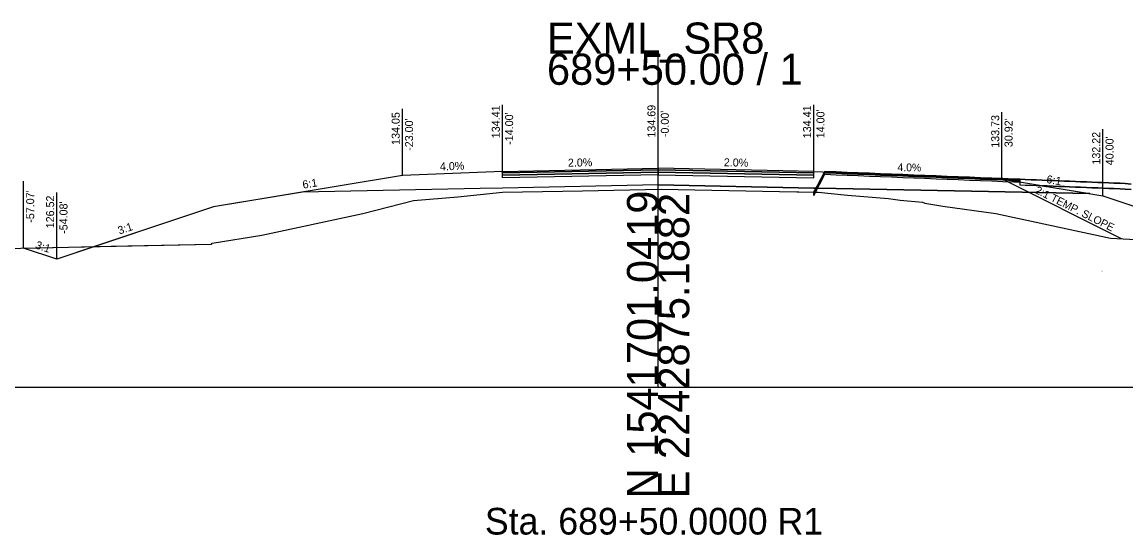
# Model space of a CAD drawing. Extents: x -26 to 1303, y -13 to 9563.
# Drawn here: x 92.8 to 192.1, y 4986.7 to 5032.8 of the extents above; entities that cross this region are included whole.
import ezdxf

# ---------------------------------------------------------------- set-up
doc = ezdxf.new("R2010")
doc.units = 0
for name, color, linetype in [('ASHPALT_12_5MM1', 7, 'Continuous'), ('ASPHALT_19MM1', 7, 'Continuous'), ('ASPHALT_9_5MM1', 7, 'Continuous'), ('CONST_LV3', 7, 'Continuous'), ('Default', 7, 'Continuous'), ('Draft_XS_Text', 7, 'Continuous'), ('DTM_P_FINISHED_GRADE', 7, 'Continuous'), ('DTM_TEMP_DROP', 7, 'Continuous'), ('DTM_X_BOUNDARY', 7, 'Continuous'), ('DTM_X_GROUND', 7, 'Continuous'), ('X_PROFILES_1', 7, 'Continuous'), ('XS_CELL', 7, 'Continuous'), ('XS_M_SHAPES_EARTHWORK', 7, 'Continuous'), ('XS_P_DR_ASPHALT', 7, 'Continuous'), ('XS_P_DR_ASPHALT_B', 7, 'Continuous'), ('XS_P_DR_GRAVEL', 7, 'Continuous'), ('XS_P_GROUND', 7, 'Continuous'), ('XS_P_SHOULDER', 7, 'Continuous'), ('XS_P_SUBGRADE_GRANULAR', 7, 'Continuous'), ('XS_P_TX_CLEARZONE', 7, 'Continuous'), ('XS_P_TX_FS_BS', 7, 'Continuous')]:
    doc.layers.add(name, color=color, linetype=linetype)

msp = doc.modelspace()

# ---------------------------------------------------------------- linework, layer by layer
at = {"layer": 'ASHPALT_12_5MM1'}
for points in [[(150, 5019.565), (150, 5019.355), (136, 5019.075), (136, 5019.285), (150, 5019.565)], [(150, 5019.565), (150, 5019.355), (164, 5019.075), (164, 5019.285), (150, 5019.565)]]:
    msp.add_lwpolyline(points, dxfattribs=at)
at = {"layer": 'ASPHALT_19MM1'}
for points in [[(150, 5019.355), (150, 5019.105), (136, 5018.825), (136, 5019.075), (150, 5019.355)], [(150, 5019.355), (150, 5019.105), (164, 5018.825), (164, 5019.075), (150, 5019.355)]]:
    msp.add_lwpolyline(points, dxfattribs=at)
at = {"layer": 'ASPHALT_9_5MM1'}
for points in [[(150, 5019.69), (150, 5019.565), (136, 5019.285), (136, 5019.41), (150, 5019.69)], [(150, 5019.69), (150, 5019.565), (164, 5019.285), (164, 5019.41), (150, 5019.69)]]:
    msp.add_lwpolyline(points, dxfattribs=at)
at = {"layer": 'CONST_LV3'}
msp.add_lwpolyline([(118, 5017.55), (110, 5016.216)], dxfattribs=at)
at = {"layer": 'DTM_P_FINISHED_GRADE'}
for points in [[(164, 5017.506), (165, 5019.405), (166, 5019.365), (167, 5019.325), (168, 5019.285), (169, 5019.245), (170, 5019.205), (171, 5019.165), (172, 5019.125), (173, 5019.085), (174, 5019.045), (175, 5019.005), (176, 5018.965), (177, 5018.925), (178, 5018.885), (179, 5018.845), (180, 5018.805), (181, 5018.765), (182, 5018.725), (182.543, 5018.704)], [(182.543, 5018.704), (183, 5018.685), (183.543, 5018.664), (184, 5018.645), (184.543, 5018.624), (185, 5018.605), (185.543, 5018.584), (186, 5018.565), (186.543, 5018.544), (187, 5018.525), (187.543, 5018.504), (188, 5018.485), (188.543, 5018.464), (189, 5018.445), (189.543, 5018.424), (190, 5018.405), (190.543, 5018.384), (191, 5018.365), (191.543, 5018.344), (192, 5018.325), (192.543, 5018.278)]]:
    msp.add_lwpolyline(points, dxfattribs=at)
at = {"layer": 'DTM_X_GROUND'}
msp.add_lwpolyline([(86.948, 5012.387), (96.964, 5012.61), (109.831, 5012.854), (109.9, 5012.954), (114.36, 5013.679), (123.451, 5015.61), (128.011, 5016.799), (131.983, 5017.133), (136.007, 5017.531), (143.203, 5017.677), (150.264, 5017.809), (160.911, 5017.613), (164.399, 5017.53), (167.029, 5017.267), (170.727, 5016.964), (171.762, 5016.835), (173.766, 5016.638), (173.979, 5016.565), (175.597, 5016.298), (180.383, 5015.638), (190.7, 5013.405), (200.917, 5012.876)], dxfattribs=at)
at = {"layer": 'XS_CELL'}
for p, q in [((150, 5000), (150, 5030)), ((0, 5000), (150, 5000)), ((150, 5000), (300, 5000))]:
    msp.add_line(p, q, dxfattribs=at)
at = {"layer": 'XS_M_SHAPES_EARTHWORK'}
for points in [[(99.314, 5012.655), (109.831, 5012.854), (109.9, 5012.954), (114.36, 5013.679), (123.451, 5015.61), (128.011, 5016.799), (131.983, 5017.133), (136.007, 5017.531), (143.203, 5017.677), (150.264, 5017.809), (160.911, 5017.613), (164.017, 5017.539), (164.21, 5017.906), (164, 5017.91), (150, 5018.19), (136, 5017.91), (134, 5017.87), (118, 5017.55), (110, 5016.216)], [(164.017, 5017.539), (164.147, 5017.536), (164, 5017.256), (164, 5017.381), (164, 5017.506)], [(92.926, 5012.52), (96.964, 5012.61), (99.314, 5012.655), (95.918, 5011.523)]]:
    msp.add_lwpolyline(points, close=True, dxfattribs=at)
msp.add_lwpolyline([(192.543, 5017.778), (192, 5017.825), (191.543, 5017.844), (191, 5017.865), (190.543, 5017.884), (190, 5017.905), (189.543, 5017.924), (189, 5017.945), (188.543, 5017.964), (188, 5017.985), (187.543, 5018.004), (187, 5018.025), (186.543, 5018.044), (186, 5018.065), (185.543, 5018.084), (185, 5018.105), (184.585, 5018.122), (188.837, 5017.413), (166, 5017.87), (164.341, 5017.903), (164.147, 5017.536), (164.399, 5017.53), (167.029, 5017.267), (170.727, 5016.964), (171.762, 5016.835), (173.766, 5016.638), (173.979, 5016.565), (175.597, 5016.298), (180.383, 5015.638), (190.7, 5013.405), (200.917, 5012.876)], dxfattribs=at)
at = {"layer": 'XS_P_DR_ASPHALT'}
msp.add_lwpolyline([(164, 5017.506), (164, 5017.381), (165, 5019.28), (165, 5019.28), (166, 5019.24), (166, 5019.24), (167, 5019.2), (167, 5019.2), (168, 5019.16), (168, 5019.16), (169, 5019.12), (169, 5019.12), (170, 5019.08), (170, 5019.08), (171, 5019.04), (171, 5019.04), (172, 5019), (172, 5019), (173, 5018.96), (173, 5018.96), (173, 5018.96), (174, 5018.92), (175, 5018.88), (175, 5018.88), (176, 5018.84), (176, 5018.84), (177, 5018.8), (177, 5018.8), (177, 5018.8), (178, 5018.76), (178, 5018.76), (179, 5018.72), (179, 5018.72), (180, 5018.68), (180, 5018.68), (181, 5018.64), (182, 5018.6), (182.543, 5018.579), (182.543, 5018.704), (182, 5018.725), (181, 5018.765), (180, 5018.805), (180, 5018.805), (179, 5018.845), (179, 5018.845), (178, 5018.885), (178, 5018.885), (177, 5018.925), (177, 5018.925), (177, 5018.925), (176, 5018.965), (176, 5018.965), (175, 5019.005), (175, 5019.005), (174, 5019.045), (173, 5019.085), (173, 5019.085), (173, 5019.085), (172, 5019.125), (172, 5019.125), (171, 5019.165), (171, 5019.165), (170, 5019.205), (170, 5019.205), (169, 5019.245), (169, 5019.245), (168, 5019.285), (168, 5019.285), (167, 5019.325), (167, 5019.325), (166, 5019.365), (166, 5019.365), (165, 5019.405), (165, 5019.405), (164, 5017.506)], dxfattribs=at)
at = {"layer": 'XS_P_DR_ASPHALT_B'}
msp.add_lwpolyline([(164, 5017.381), (164, 5017.256), (165, 5019.155), (165, 5019.155), (166, 5019.115), (166, 5019.115), (167, 5019.075), (167, 5019.075), (168, 5019.035), (168, 5019.035), (169, 5018.995), (169, 5018.995), (170, 5018.955), (170, 5018.955), (171, 5018.915), (171, 5018.915), (172, 5018.875), (172, 5018.875), (173, 5018.835), (173, 5018.835), (173, 5018.835), (174, 5018.795), (175, 5018.755), (175, 5018.755), (176, 5018.715), (176, 5018.715), (177, 5018.675), (177, 5018.675), (177, 5018.675), (178, 5018.635), (178, 5018.635), (179, 5018.595), (179, 5018.595), (180, 5018.555), (180, 5018.555), (181, 5018.515), (182, 5018.475), (182.543, 5018.454), (182.543, 5018.579), (182, 5018.6), (181, 5018.64), (180, 5018.68), (180, 5018.68), (179, 5018.72), (179, 5018.72), (178, 5018.76), (178, 5018.76), (177, 5018.8), (177, 5018.8), (177, 5018.8), (176, 5018.84), (176, 5018.84), (175, 5018.88), (175, 5018.88), (174, 5018.92), (173, 5018.96), (173, 5018.96), (173, 5018.96), (172, 5019), (172, 5019), (171, 5019.04), (171, 5019.04), (170, 5019.08), (170, 5019.08), (169, 5019.12), (169, 5019.12), (168, 5019.16), (168, 5019.16), (167, 5019.2), (167, 5019.2), (166, 5019.24), (166, 5019.24), (165, 5019.28), (165, 5019.28), (164, 5017.381)], dxfattribs=at)
at = {"layer": 'XS_P_DR_GRAVEL'}
for points in [[(182.543, 5018.704), (182.543, 5018.204), (183, 5018.185), (183.543, 5018.164), (184, 5018.145), (184.543, 5018.124), (184.543, 5018.124), (185, 5018.105), (185.543, 5018.084), (186, 5018.065), (186, 5018.065), (186.543, 5018.044), (186.543, 5018.044), (187, 5018.025), (187.543, 5018.004), (187.543, 5018.004), (188, 5017.985), (188.543, 5017.964), (188.543, 5017.964), (189, 5017.945), (189.543, 5017.924), (190, 5017.905), (190.543, 5017.884), (190.543, 5017.884), (191, 5017.865), (191.543, 5017.844), (192, 5017.825), (192.543, 5017.778)], [(192.543, 5018.278), (192, 5018.325), (191.543, 5018.344), (191, 5018.365), (190.543, 5018.384), (190.543, 5018.384), (190, 5018.405), (189.543, 5018.424), (189, 5018.445), (188.543, 5018.464), (188.543, 5018.464), (188, 5018.485), (187.543, 5018.504), (187.543, 5018.504), (187, 5018.525), (186.543, 5018.544), (186.543, 5018.544), (186, 5018.565), (186, 5018.565), (185.543, 5018.584), (185, 5018.605), (184.543, 5018.624), (184.543, 5018.624), (184, 5018.645), (183.543, 5018.664), (183, 5018.685), (182.543, 5018.704)]]:
    msp.add_lwpolyline(points, dxfattribs=at)
at = {"layer": 'XS_P_GROUND'}
for points in [[(126.998, 5019.05), (110, 5016.216), (95.918, 5011.523)], [(180.919, 5018.733), (190, 5017.219), (204.104, 5012.519)], [(95.918, 5011.523), (92.926, 5012.52)]]:
    msp.add_lwpolyline(points, dxfattribs=at)
at = {"layer": 'XS_P_SHOULDER'}
msp.add_line((191.676, 5013.355), (180.919, 5018.733), dxfattribs=at)
for points in [[(136, 5019.41), (126.998, 5019.05)], [(164, 5019.41), (180.919, 5018.733)]]:
    msp.add_lwpolyline(points, dxfattribs=at)
at = {"layer": 'XS_P_SUBGRADE_GRANULAR'}
for points in [[(136, 5017.91), (134, 5017.87), (118, 5017.55)], [(150, 5018.19), (136, 5017.91)], [(150, 5018.19), (164, 5017.91)], [(164, 5017.91), (166, 5017.87), (188.837, 5017.413)]]:
    msp.add_lwpolyline(points, dxfattribs=at)
at = {"layer": 'XS_P_TX_CLEARZONE'}
for p, q in [((150, 5019.69), (150, 5025.69)), ((150, 5019.69), (150, 5025.69)), ((126.998, 5019.05), (126.998, 5025.05)), ((126.998, 5019.05), (126.998, 5025.05)), ((136, 5019.41), (136, 5025.41)), ((164, 5019.41), (164, 5025.41)), ((180.919, 5018.733), (180.919, 5024.733)), ((190, 5017.219), (190, 5023.219)), ((92.926, 5012.52), (92.926, 5018.52)), ((95.918, 5011.523), (95.918, 5017.523))]:
    msp.add_line(p, q, dxfattribs=at)

# ---------------------------------------------------------------- texts
at = {"layer": 'Default'}
for p in [(92.887, 5012.46), (95.879, 5011.463), (189.876, 5010.371), (189.876, 5010.371)]:
    msp.add_text('X', height=0.12, dxfattribs=at).set_placement(p)
at = {"layer": 'Draft_XS_Text'}
msp.add_text('Sta. 689+50.0000 R1', height=2.4, dxfattribs=at).set_placement((134.42, 4986.75))
at = {"layer": 'DTM_TEMP_DROP'}
for p in [(149.961, 5019.63), (135.961, 5019.35), (163.961, 5019.35), (163.961, 5017.446)]:
    msp.add_text('X', height=0.12, dxfattribs=at).set_placement(p)
at = {"layer": 'DTM_X_BOUNDARY'}
for p in [(126.958, 5018.99), (180.88, 5018.673)]:
    msp.add_text('X', height=0.12, dxfattribs=at).set_placement(p)
at = {"layer": 'X_PROFILES_1'}
msp.add_text('X', height=0.12, dxfattribs=at).set_placement((189.961, 5017.159))
at = {"layer": 'XS_CELL'}
for s, p in [('EXML_SR8', (140, 5030)), ('689+50.00 / 1', (140, 5027.2))]:
    msp.add_text(s, height=2.8, dxfattribs=at).set_placement(p)
for s, p in [('N 1541701.0419', (150, 4990)), ('E 2242875.1882', (152.8, 4990))]:
    msp.add_text(s, height=2.8, rotation=90, dxfattribs=at).set_placement(p)
at = {"layer": 'XS_P_TX_CLEARZONE'}
for s, p in [('134.05', (126.758, 5021.797)), ('134.05', (126.758, 5021.797)), ('134.41', (135.76, 5022.396)), ("-14.00'", (136.96, 5021.806)), ('134.69', (149.76, 5022.454)), ('134.69', (149.76, 5022.454)), ("-0.00'", (150.96, 5022.494)), ("-0.00'", (150.96, 5022.494)), ('134.41', (163.76, 5022.396)), ("14.00'", (164.96, 5022.396)), ("-23.00'", (127.958, 5021.265)), ("-23.00'", (127.958, 5021.265)), ('133.73', (180.679, 5021.537)), ("30.92'", (181.879, 5021.594)), ('132.22', (189.76, 5020.024)), ("40.00'", (190.96, 5019.967)), ("-57.07'", (93.886, 5014.792)), ('126.52', (95.678, 5014.293)), ("-54.08'", (96.878, 5013.794))]:
    msp.add_text(s, height=0.72, rotation=90, dxfattribs=at).set_placement(p)
at = {"layer": 'XS_P_TX_FS_BS'}
for s, height, rotation, p in [('4.0%', 0.72, 2.29061, (130.386, 5019.486)), ('2.0%', 0.72, 1.14576, (141.892, 5019.828)), ('2.0%', 0.72, 358.85424, (155.904, 5019.872)), ('4.0%', 0.7, 358.85424, (171.524, 5019.444)), ('6:1', 0.72, 9.46418, (118.077, 5017.852)), ('6:1', 0.72, 350.53582, (184.888, 5018.376)), ('2:1 TEMP. SLOPE', 0.7, 333.21625, (183.842, 5017.501)), ('3:1', 0.72, 18.43323, (101.541, 5013.728)), ('3:1', 0.72, 341.56507, (93.936, 5012.5))]:
    msp.add_text(s, height=height, rotation=rotation, dxfattribs=at).set_placement(p)

doc.saveas('drawing.dxf')
